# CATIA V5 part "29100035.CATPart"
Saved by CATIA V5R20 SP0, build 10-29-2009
Part number: 29100035
Definition: NONE
Nomenclature: 29100035
Source: Unknown
Description: 29100035
Bounding box of the stored display mesh (mm): x -17.5 to 44.548, y -64 to 98.548, z -54 to 54
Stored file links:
  C:\Users\Utente\Desktop\IO LAVORO\3D X SITO CF\X SITO\PLASTICA\RF1\29100035.CATPart

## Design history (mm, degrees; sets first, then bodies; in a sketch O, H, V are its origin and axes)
Body1 "29100035" (main body)
  Solid1: solid without history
